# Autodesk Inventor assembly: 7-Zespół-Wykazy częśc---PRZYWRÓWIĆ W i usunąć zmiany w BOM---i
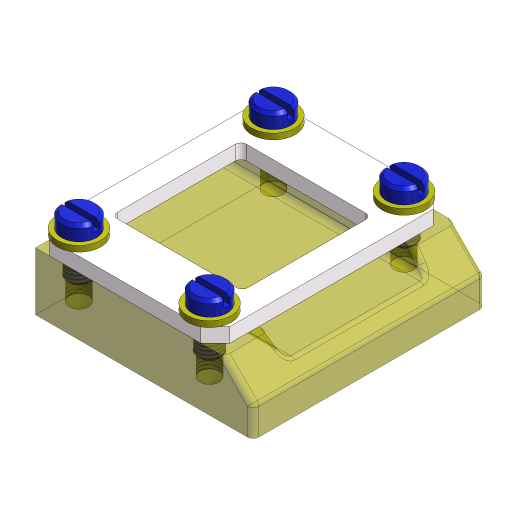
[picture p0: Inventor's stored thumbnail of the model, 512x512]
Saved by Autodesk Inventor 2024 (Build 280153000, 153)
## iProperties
Created: 2023-03
Part Number: 7-Zespół-Wykazy częśc---PRZYWRÓWIĆ W i usunąć zmiany w BOM---i
Document SubType Name: Assembly
Designer: Andrzej Jaskulski
Stock Number: 7-Zespół-Wykazy części
Mass: 113.21 g
Surface Area: 319.961 cm^2
Volume: 113.21 cm^3
Density: 1 g/cm^3
Checked By: A.J.
Engr Approved By: Andrzej Jaskulski
Mfg Approved By: Andrzej Jaskulski
Authority: A.J.
Company: ATC
Control State: 0
Master: False
Checked Out: False
Shininess: 20.0
Length Units: 11269
Angle Units: 11279
Time Units: 11290
Mass Units: 11283
Length Display Precision: 3
Angle Display Precision: 2
Compacted: True
Density: 0.0
Volumn: 0.0
Area: 0.0
PropertySet Name: Model Information
Title: A.J.: Kurs R2024-MEP
Author: Andrzej Jaskulski
Revision Number: 1/24
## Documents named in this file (3)
- C:\Users\AndJas\Documents\R2024-MEP\Obszar roboczy\7-Zespół-Wykazy częśc---PRZYWRÓWIĆ W i usunąć zmiany w BOM---i.iam
- C:\Users\AndJas\Documents\R2024-MEP\Obszar roboczy\P.ipt
- C:\Users\AndJas\Documents\R2024-MEP\Obszar roboczy\Mocowanie.iam
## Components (2 placed, 2 different names)
1. Płyta — Wstaw:1, Wstaw:2
2. Mocowanie:1 [sub-assembly] — Wstaw:1, Wstaw:2
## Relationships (2: Insert 2)
- Wstaw:1 [Insert]: Płyta ↔ Mocowanie:1
- Wstaw:2 [Insert]: Płyta ↔ Mocowanie:1
